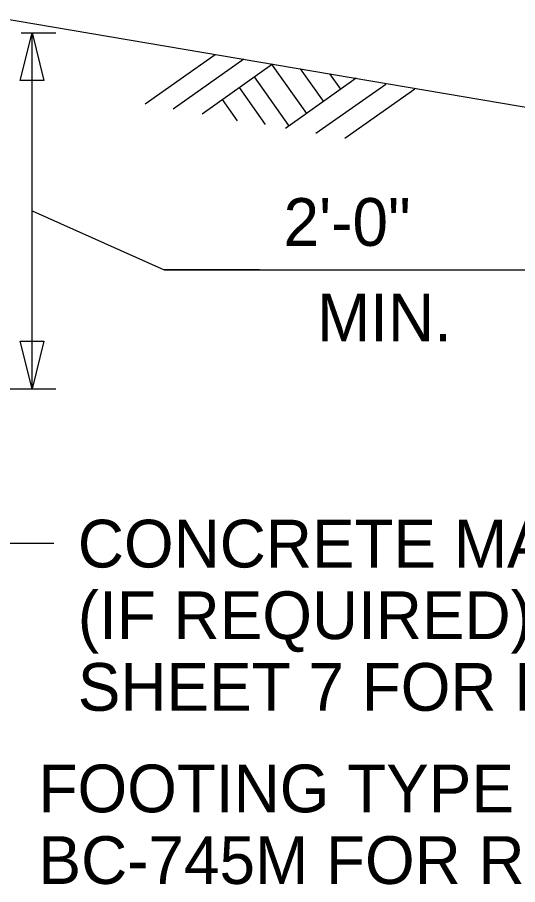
# Model space of a CAD drawing. Extents: x 3831399 to 3833095, y 499014 to 500202.
# Drawn here: x 3832778.2 to 3832808.7, y 499745.8 to 499798.7 of the extents above; entities that cross this region are included whole.
import ezdxf

# ---------------------------------------------------------------- set-up
doc = ezdxf.new("R2010")
doc.units = 0
doc.layers.add('DIM TXT', color=7, linetype='Continuous')
doc.layers.add('grade', color=7, linetype='Continuous')

msp = doc.modelspace()

# ---------------------------------------------------------------- linework, layer by layer
at = {"layer": 'DIM TXT'}
for p, q in [((3832778.446, 499797.713), (3832780.566, 499797.713)), ((3832779.111, 499776.025), (3832779.111, 499797.713)), ((3832779.111, 499786.869), (3832787.163, 499783.282)), ((3832787.163, 499783.282), (3832823.994, 499783.282)), ((3832792.982, 499783.282), (3832787.163, 499783.282)), ((3832794.437, 499783.282), (3832807.841, 499783.282)), ((3832773.29, 499776.025), (3832780.566, 499776.025)), ((3832780.447, 499766.594), (3832774.627, 499766.594))]:
    msp.add_line(p, q, dxfattribs=at)
for points in [[(3832778.384, 499794.804), (3832779.111, 499797.713), (3832779.839, 499794.804)], [(3832779.839, 499778.935), (3832779.111, 499776.025), (3832778.384, 499778.935)]]:
    msp.add_lwpolyline(points, close=True, dxfattribs=at)
at = {"layer": 'grade'}
for p, q in [((3832776.991, 499798.661), (3832812.016, 499792.707)), ((3832786.007, 499793.382), (3832790.279, 499796.402)), ((3832787.713, 499793.089), (3832792.008, 499796.125)), ((3832789.477, 499792.787), (3832793.771, 499795.822)), ((3832793.693, 499795.836), (3832795.836, 499792.804)), ((3832795.457, 499795.533), (3832796.853, 499793.558)), ((3832797.241, 499795.226), (3832797.907, 499794.285)), ((3832792.646, 499795.027), (3832794.741, 499792.064)), ((3832794.553, 499791.915), (3832798.871, 499794.966)), ((3832796.415, 499791.594), (3832800.664, 499794.598)), ((3832791.728, 499794.378), (3832793.319, 499792.126)), ((3832798.179, 499791.292), (3832802.428, 499794.295)), ((3832790.694, 499793.647), (3832791.603, 499792.361))]:
    msp.add_line(p, q, dxfattribs=at)

# ---------------------------------------------------------------- texts
at = {"layer": 'DIM TXT'}
for s, height, p in [('2\'-0"', 2.9099, (3832794.437, 499784.737)), ('MIN.', 2.9099, (3832796.477, 499778.917)), ('CONCRETE MAINTAINER PAD', 2.90992, (3832781.902, 499765.139)), ('(IF REQUIRED). SEE ITS-1201M', 2.90992, (3832781.902, 499760.774)), ('SHEET 7 FOR DETAILS.', 2.90992, (3832781.902, 499756.409)), ('FOOTING TYPE (SIZE). SEE', 2.90992, (3832779.506, 499750.222)), ('BC-745M FOR REINFORCEMENT', 2.90992, (3832779.506, 499745.857))]:
    msp.add_text(s, height=height, dxfattribs=at).set_placement(p)

doc.saveas('drawing.dxf')
